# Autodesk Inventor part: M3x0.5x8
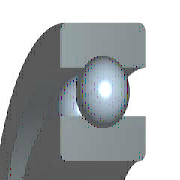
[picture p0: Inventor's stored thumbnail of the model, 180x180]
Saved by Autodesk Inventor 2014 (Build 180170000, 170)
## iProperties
Created: 2009-02
Part Number: M3x0.5x8
Material: 강, 연강
Description: 깊은 그루브 볼 베어링
Document SubType Name: Modeling
Standard: KS B 2023
Designer: KYOUNG IL JANG
Standards Organization: KS
Language: ko-KR
Size Designation: 6202 - 15 x 35 x 11
Categories: <MemberInstance><Categories><Category DisplayName="샤프트 부품" InternalName="7f7aeb1f-a693-4053-b835-cee3144e0d98" Mnemonic="SHFT"><Category DisplayName="베어링" Inter
Density: 7.86 g/cm^3
Mass: 45.8725 g
Surface Area: 51.5584 cm^2
Volume: 5.83619 cm^3
Vendor: CBT Solutions
Appearance: 강철
Company: 한국ATC센터
IsCustomPart: 1
Author: KYOUNG IL JANG
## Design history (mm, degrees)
sketch "스케치" dims "d0" = 5.2 (= -0.26 x WD + 0.26 x BD)
  geometry: L1 (2.9, 12.5)-(8.1, 12.5); L2 (5.5, 12.5)-(5.5, 9.9); L3 (5.5, 12.5)-(5.5, 15.1); L4 (3.568, 10.76)-(0, 10.76); L5 (0, 7.5)-(11, 7.5); L6 (3.568, 14.24)-(0, 14.24); L7 (0, 17.5)-(11, 17.5); L8 (11, 7.5)-(11, 10.76); L9 (7.432, 10.76)-(11, 10.76); L10 (7.432, 14.24)-(11, 14.24); L11 (11, 17.5)-(11, 14.24); L12 (-1.4, 0)-(8.4, 0) reference; L13 (0, -0.3)-(0, 5.3) reference
  constraints: 22 end point, 4 point on line, 2 collinear, 2 perpendicular, 2 symmetric about line, 1 midpoint, 1 parallel, 14 other
  dimensions: "d9" = 15 diameter of L5 L12 (= WD); "d11" = 35 diameter of L7 L12 (= BD); "d12" = 11 distance between parallel lines of L8 L13 (= KB); "d13" = 21.52 diameter of L9 L12 (= 0.326 x BD + 0.674 x WD)
revolve "본체" stored, may be unused: angle "d6" = 90 deg
revolve "볼" stored, may be unused: angle "d7" = 90 deg
pattern_circular "IDS_ARRAYBALL[SIMPL:T]" dims angle "d3" = 360 deg
body "Solid1"
fillet "모깎기1" dims "d1" = 0.6 (= KRS)
other parameters: "WD" = 15 [user parameter; used in 5 equation terms], "BD" = 35 [user parameter; used in 5 equation terms], "KB" = 11 [user parameter; used in 1 equation term], "KRS" = 0.6 [user parameter; used in 1 equation term], "d4" = 0, "d5" = 0, "d8" = 0, "d14" = 0, "d15" = 0, "BBA" = 0 [user parameter], "BC0" = 3750000 [user parameter], "BC" = 7800000 [user parameter], "BR" = 17.5 (= 0.5 x BD) [user parameter], "WR" = 7.5 (= 0.5 x WD) [user parameter]
